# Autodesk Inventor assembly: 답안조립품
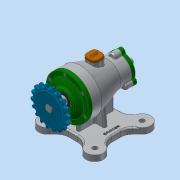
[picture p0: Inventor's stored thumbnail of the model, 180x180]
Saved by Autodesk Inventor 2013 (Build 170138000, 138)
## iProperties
Created: 2018-03
Part Number: 답안조립품
Document SubType Name: Assembly
Designer: dgall
Author: dgall
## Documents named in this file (15)
- C:\Users\dgall\Desktop\480307V1012\답안조립품.iam
- C:\Users\dgall\Desktop\480307V1012\본체.ipt
- C:\Users\dgall\Desktop\480307V1012\뒤커버.ipt
- C:\Users\dgall\Desktop\480307V1012\마개.ipt
- C:\Users\dgall\Desktop\480307V1012\베어링-6200.ipt
- C:\Users\dgall\Desktop\480307V1012\베어링-6203.ipt
- C:\Users\dgall\Desktop\480307V1012\볼트 M4 x 12.ipt
- 볼트 M4 x 12.ipt
- C:\Users\dgall\Desktop\480307V1012\스프로킷.ipt
- C:\Users\dgall\Desktop\480307V1012\앞커버.ipt
- C:\Users\dgall\Desktop\480307V1012\오일 실 10 20 7.ipt
- C:\Users\dgall\Desktop\480307V1012\오일 실 17 30 8.ipt
- C:\Users\dgall\Desktop\480307V1012\축.ipt
- C:\Users\dgall\Desktop\480307V1012\키 5 x 5.ipt
- 키 5 x 5.ipt
